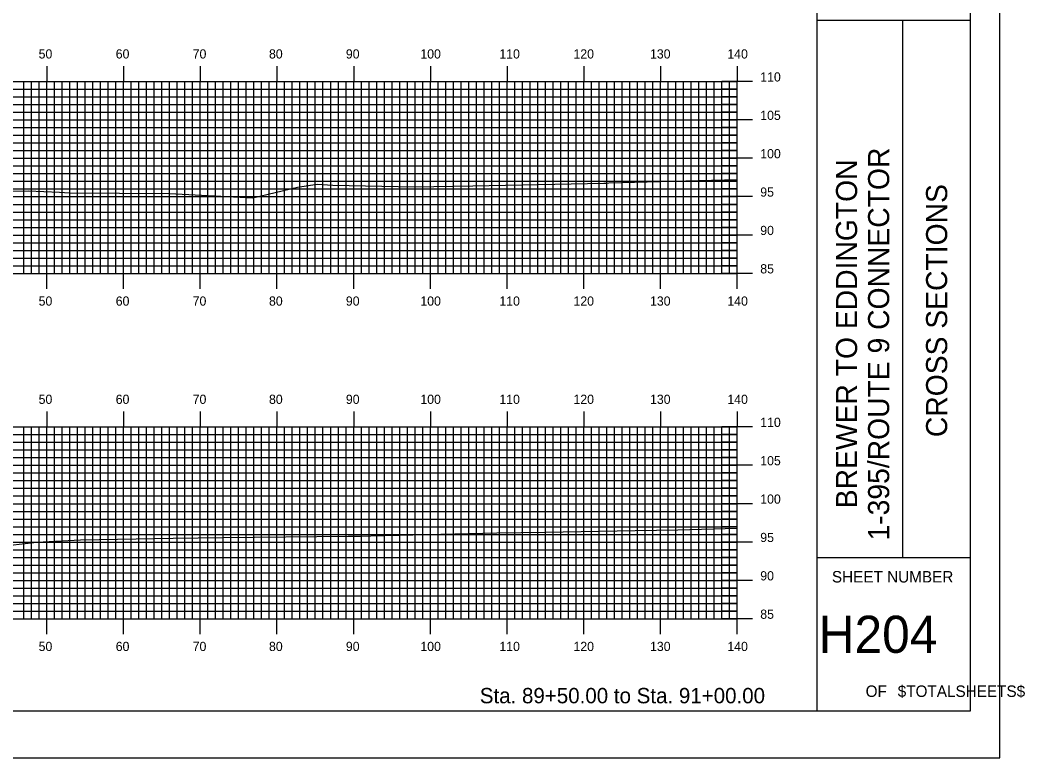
# Model space of a CAD drawing. Extents: x 1764546 to 1764889, y 442591 to 442811.
# Drawn here: x 1764757.9 to 1764888.8, y 442590.5 to 442686.7 of the extents above; entities that cross this region are included whole.
import ezdxf

# ---------------------------------------------------------------- set-up
doc = ezdxf.new("R2010")
doc.units = 0
for name, color, linetype in [('BORDER', 7, 'Continuous'), ('H_V ANNOTATION', 7, 'Continuous'), ('MAJOR', 7, 'Continuous'), ('MINOR', 7, 'Continuous'), ('PLOT BOUNDARY', 7, 'Continuous'), ('S_Roadway_Centerline', 7, 'Continuous')]:
    doc.layers.add(name, color=color, linetype=linetype)

msp = doc.modelspace()

# ---------------------------------------------------------------- linework, layer by layer
at = {"layer": 'BORDER'}
for p, q in [((1764861.74, 442596.67), (1764861.74, 442806.67)), ((1764861.74, 442686.67), (1764881.74, 442686.67)), ((1764872.93, 442616.67), (1764872.93, 442686.67)), ((1764861.74, 442616.67), (1764881.74, 442616.67))]:
    msp.add_line(p, q, dxfattribs=at)
msp.add_lwpolyline([(1764561.74, 442596.67), (1764881.74, 442596.67), (1764881.74, 442806.67), (1764561.74, 442806.67)], close=True, dxfattribs=at)
at = {"layer": 'MAJOR'}
for p, q in [((1764761.34, 442680.67), (1764761.34, 442678.67)), ((1764771.34, 442680.67), (1764771.34, 442678.67)), ((1764781.34, 442680.67), (1764781.34, 442678.67)), ((1764791.34, 442680.67), (1764791.34, 442678.67)), ((1764801.34, 442680.67), (1764801.34, 442678.67)), ((1764811.34, 442680.67), (1764811.34, 442678.67)), ((1764821.34, 442680.67), (1764821.34, 442678.67)), ((1764831.34, 442680.67), (1764831.34, 442678.67)), ((1764841.34, 442680.67), (1764841.34, 442678.67)), ((1764851.34, 442680.67), (1764851.34, 442678.67)), ((1764571.34, 442678.67), (1764851.34, 442678.67)), ((1764571.34, 442678.67), (1764851.34, 442678.67)), ((1764761.34, 442653.67), (1764761.34, 442678.67)), ((1764771.34, 442653.67), (1764771.34, 442678.67)), ((1764781.34, 442653.67), (1764781.34, 442678.67)), ((1764791.34, 442653.67), (1764791.34, 442678.67)), ((1764801.34, 442653.67), (1764801.34, 442678.67)), ((1764811.34, 442653.67), (1764811.34, 442678.67)), ((1764821.34, 442653.67), (1764821.34, 442678.67)), ((1764831.34, 442653.67), (1764831.34, 442678.67)), ((1764841.34, 442653.67), (1764841.34, 442678.67)), ((1764853.35, 442678.67), (1764849.34, 442678.67)), ((1764851.34, 442653.67), (1764851.34, 442678.67)), ((1764851.34, 442653.67), (1764851.34, 442678.67)), ((1764571.34, 442673.67), (1764851.34, 442673.67)), ((1764853.35, 442673.67), (1764849.34, 442673.67)), ((1764571.34, 442668.67), (1764851.34, 442668.67)), ((1764853.35, 442668.67), (1764849.34, 442668.67)), ((1764571.34, 442663.67), (1764851.34, 442663.67)), ((1764853.35, 442663.67), (1764849.34, 442663.67)), ((1764571.34, 442658.67), (1764851.34, 442658.67)), ((1764853.35, 442658.67), (1764849.34, 442658.67)), ((1764571.34, 442653.67), (1764851.34, 442653.67)), ((1764571.34, 442653.67), (1764851.34, 442653.67)), ((1764761.34, 442651.66), (1764761.34, 442653.67)), ((1764771.34, 442651.66), (1764771.34, 442653.67)), ((1764781.34, 442651.66), (1764781.34, 442653.67)), ((1764791.34, 442651.66), (1764791.34, 442653.67)), ((1764801.34, 442651.66), (1764801.34, 442653.67)), ((1764811.34, 442651.66), (1764811.34, 442653.67)), ((1764821.34, 442651.66), (1764821.34, 442653.67)), ((1764831.34, 442651.66), (1764831.34, 442653.67)), ((1764841.34, 442651.66), (1764841.34, 442653.67)), ((1764853.35, 442653.67), (1764849.34, 442653.67)), ((1764851.34, 442651.66), (1764851.34, 442653.67)), ((1764761.34, 442635.67), (1764761.34, 442633.67)), ((1764771.34, 442635.67), (1764771.34, 442633.67)), ((1764781.34, 442635.67), (1764781.34, 442633.67)), ((1764791.34, 442635.67), (1764791.34, 442633.67)), ((1764801.34, 442635.67), (1764801.34, 442633.67)), ((1764811.34, 442635.67), (1764811.34, 442633.67)), ((1764821.34, 442635.67), (1764821.34, 442633.67)), ((1764831.34, 442635.67), (1764831.34, 442633.67)), ((1764841.34, 442635.67), (1764841.34, 442633.67)), ((1764851.34, 442635.67), (1764851.34, 442633.67)), ((1764571.34, 442633.67), (1764851.34, 442633.67)), ((1764571.34, 442633.67), (1764851.34, 442633.67)), ((1764761.34, 442608.67), (1764761.34, 442633.67)), ((1764771.34, 442608.67), (1764771.34, 442633.67)), ((1764781.34, 442608.67), (1764781.34, 442633.67)), ((1764791.34, 442608.67), (1764791.34, 442633.67)), ((1764801.34, 442608.67), (1764801.34, 442633.67)), ((1764811.34, 442608.67), (1764811.34, 442633.67)), ((1764821.34, 442608.67), (1764821.34, 442633.67)), ((1764831.34, 442608.67), (1764831.34, 442633.67)), ((1764841.34, 442608.67), (1764841.34, 442633.67)), ((1764853.35, 442633.67), (1764849.34, 442633.67)), ((1764851.34, 442608.67), (1764851.34, 442633.67)), ((1764851.34, 442608.67), (1764851.34, 442633.67)), ((1764571.34, 442628.67), (1764851.34, 442628.67)), ((1764853.35, 442628.67), (1764849.34, 442628.67)), ((1764571.34, 442623.67), (1764851.34, 442623.67)), ((1764853.35, 442623.67), (1764849.34, 442623.67)), ((1764571.34, 442618.67), (1764851.34, 442618.67)), ((1764853.35, 442618.67), (1764849.34, 442618.67)), ((1764571.34, 442613.67), (1764851.34, 442613.67)), ((1764853.35, 442613.67), (1764849.34, 442613.67)), ((1764571.34, 442608.67), (1764851.34, 442608.67)), ((1764571.34, 442608.67), (1764851.34, 442608.67)), ((1764761.34, 442606.66), (1764761.34, 442608.67)), ((1764771.34, 442606.66), (1764771.34, 442608.67)), ((1764781.34, 442606.66), (1764781.34, 442608.67)), ((1764791.34, 442606.66), (1764791.34, 442608.67)), ((1764801.34, 442606.66), (1764801.34, 442608.67)), ((1764811.34, 442606.66), (1764811.34, 442608.67)), ((1764821.34, 442606.66), (1764821.34, 442608.67)), ((1764831.34, 442606.66), (1764831.34, 442608.67)), ((1764841.34, 442606.66), (1764841.34, 442608.67)), ((1764853.35, 442608.67), (1764849.34, 442608.67)), ((1764851.34, 442606.66), (1764851.34, 442608.67))]:
    msp.add_line(p, q, dxfattribs=at)
at = {"layer": 'MINOR'}
for p, q in [((1764758.34, 442653.67), (1764758.34, 442678.67)), ((1764759.34, 442653.67), (1764759.34, 442678.67)), ((1764760.34, 442653.67), (1764760.34, 442678.67)), ((1764762.34, 442653.67), (1764762.34, 442678.67)), ((1764763.34, 442653.67), (1764763.34, 442678.67)), ((1764764.34, 442653.67), (1764764.34, 442678.67)), ((1764765.34, 442653.67), (1764765.34, 442678.67)), ((1764766.34, 442653.67), (1764766.34, 442678.67)), ((1764767.34, 442653.67), (1764767.34, 442678.67)), ((1764768.34, 442653.67), (1764768.34, 442678.67)), ((1764769.34, 442653.67), (1764769.34, 442678.67)), ((1764770.34, 442653.67), (1764770.34, 442678.67)), ((1764772.34, 442653.67), (1764772.34, 442678.67)), ((1764773.34, 442653.67), (1764773.34, 442678.67)), ((1764774.34, 442653.67), (1764774.34, 442678.67)), ((1764775.34, 442653.67), (1764775.34, 442678.67)), ((1764776.34, 442653.67), (1764776.34, 442678.67)), ((1764777.34, 442653.67), (1764777.34, 442678.67)), ((1764778.34, 442653.67), (1764778.34, 442678.67)), ((1764779.34, 442653.67), (1764779.34, 442678.67)), ((1764780.34, 442653.67), (1764780.34, 442678.67)), ((1764782.34, 442653.67), (1764782.34, 442678.67)), ((1764783.34, 442653.67), (1764783.34, 442678.67)), ((1764784.34, 442653.67), (1764784.34, 442678.67)), ((1764785.34, 442653.67), (1764785.34, 442678.67)), ((1764786.34, 442653.67), (1764786.34, 442678.67)), ((1764787.34, 442653.67), (1764787.34, 442678.67)), ((1764788.34, 442653.67), (1764788.34, 442678.67)), ((1764789.34, 442653.67), (1764789.34, 442678.67)), ((1764790.34, 442653.67), (1764790.34, 442678.67)), ((1764792.34, 442653.67), (1764792.34, 442678.67)), ((1764793.34, 442653.67), (1764793.34, 442678.67)), ((1764794.34, 442653.67), (1764794.34, 442678.67)), ((1764795.34, 442653.67), (1764795.34, 442678.67)), ((1764796.34, 442653.67), (1764796.34, 442678.67)), ((1764797.34, 442653.67), (1764797.34, 442678.67)), ((1764798.34, 442653.67), (1764798.34, 442678.67)), ((1764799.34, 442653.67), (1764799.34, 442678.67)), ((1764800.34, 442653.67), (1764800.34, 442678.67)), ((1764802.34, 442653.67), (1764802.34, 442678.67)), ((1764803.34, 442653.67), (1764803.34, 442678.67)), ((1764804.34, 442653.67), (1764804.34, 442678.67)), ((1764805.34, 442653.67), (1764805.34, 442678.67)), ((1764806.34, 442653.67), (1764806.34, 442678.67)), ((1764807.34, 442653.67), (1764807.34, 442678.67)), ((1764808.34, 442653.67), (1764808.34, 442678.67)), ((1764809.34, 442653.67), (1764809.34, 442678.67)), ((1764810.34, 442653.67), (1764810.34, 442678.67)), ((1764812.34, 442653.67), (1764812.34, 442678.67)), ((1764813.34, 442653.67), (1764813.34, 442678.67)), ((1764814.34, 442653.67), (1764814.34, 442678.67)), ((1764815.34, 442653.67), (1764815.34, 442678.67)), ((1764816.34, 442653.67), (1764816.34, 442678.67)), ((1764817.34, 442653.67), (1764817.34, 442678.67)), ((1764818.34, 442653.67), (1764818.34, 442678.67)), ((1764819.34, 442653.67), (1764819.34, 442678.67)), ((1764820.34, 442653.67), (1764820.34, 442678.67)), ((1764822.34, 442653.67), (1764822.34, 442678.67)), ((1764823.34, 442653.67), (1764823.34, 442678.67)), ((1764824.34, 442653.67), (1764824.34, 442678.67)), ((1764825.34, 442653.67), (1764825.34, 442678.67)), ((1764826.34, 442653.67), (1764826.34, 442678.67)), ((1764827.34, 442653.67), (1764827.34, 442678.67)), ((1764828.34, 442653.67), (1764828.34, 442678.67)), ((1764829.34, 442653.67), (1764829.34, 442678.67)), ((1764830.34, 442653.67), (1764830.34, 442678.67)), ((1764832.34, 442653.67), (1764832.34, 442678.67)), ((1764833.34, 442653.67), (1764833.34, 442678.67)), ((1764834.34, 442653.67), (1764834.34, 442678.67)), ((1764835.34, 442653.67), (1764835.34, 442678.67)), ((1764836.34, 442653.67), (1764836.34, 442678.67)), ((1764837.34, 442653.67), (1764837.34, 442678.67)), ((1764838.34, 442653.67), (1764838.34, 442678.67)), ((1764839.34, 442653.67), (1764839.34, 442678.67)), ((1764840.34, 442653.67), (1764840.34, 442678.67)), ((1764842.34, 442653.67), (1764842.34, 442678.67)), ((1764843.34, 442653.67), (1764843.34, 442678.67)), ((1764844.34, 442653.67), (1764844.34, 442678.67)), ((1764845.34, 442653.67), (1764845.34, 442678.67)), ((1764846.34, 442653.67), (1764846.34, 442678.67)), ((1764847.34, 442653.67), (1764847.34, 442678.67)), ((1764848.34, 442653.67), (1764848.34, 442678.67)), ((1764849.34, 442653.67), (1764849.34, 442678.67)), ((1764850.34, 442653.67), (1764850.34, 442678.67)), ((1764571.34, 442677.67), (1764851.34, 442677.67)), ((1764851.34, 442677.67), (1764849.34, 442677.67)), ((1764571.34, 442676.67), (1764851.34, 442676.67)), ((1764571.34, 442675.67), (1764851.34, 442675.67)), ((1764851.34, 442676.67), (1764849.34, 442676.67)), ((1764851.34, 442675.67), (1764849.34, 442675.67)), ((1764571.34, 442674.67), (1764851.34, 442674.67)), ((1764851.34, 442674.67), (1764849.34, 442674.67)), ((1764571.34, 442672.67), (1764851.34, 442672.67)), ((1764571.34, 442671.67), (1764851.34, 442671.67)), ((1764851.34, 442672.67), (1764849.34, 442672.67)), ((1764851.34, 442671.67), (1764849.34, 442671.67)), ((1764571.34, 442670.67), (1764851.34, 442670.67)), ((1764851.34, 442670.67), (1764849.34, 442670.67)), ((1764571.34, 442669.67), (1764851.34, 442669.67)), ((1764851.34, 442669.67), (1764849.34, 442669.67)), ((1764571.34, 442667.67), (1764851.34, 442667.67)), ((1764571.34, 442666.67), (1764851.34, 442666.67)), ((1764851.34, 442667.67), (1764849.34, 442667.67)), ((1764851.34, 442666.67), (1764849.34, 442666.67)), ((1764571.34, 442665.67), (1764851.34, 442665.67)), ((1764851.34, 442665.67), (1764849.34, 442665.67)), ((1764571.34, 442664.67), (1764851.34, 442664.67)), ((1764851.34, 442664.67), (1764849.34, 442664.67)), ((1764571.34, 442662.67), (1764851.34, 442662.67)), ((1764851.34, 442662.67), (1764849.34, 442662.67)), ((1764571.34, 442661.67), (1764851.34, 442661.67)), ((1764851.34, 442661.67), (1764849.34, 442661.67)), ((1764571.34, 442660.67), (1764851.34, 442660.67)), ((1764851.34, 442660.67), (1764849.34, 442660.67)), ((1764571.34, 442659.67), (1764851.34, 442659.67)), ((1764851.34, 442659.67), (1764849.34, 442659.67)), ((1764571.34, 442657.67), (1764851.34, 442657.67)), ((1764851.34, 442657.67), (1764849.34, 442657.67)), ((1764571.34, 442656.67), (1764851.34, 442656.67)), ((1764851.34, 442656.67), (1764849.34, 442656.67)), ((1764571.34, 442655.67), (1764851.34, 442655.67)), ((1764571.34, 442654.67), (1764851.34, 442654.67)), ((1764851.34, 442655.67), (1764849.34, 442655.67)), ((1764851.34, 442654.67), (1764849.34, 442654.67)), ((1764571.34, 442632.67), (1764851.34, 442632.67)), ((1764758.34, 442608.67), (1764758.34, 442633.67)), ((1764759.34, 442608.67), (1764759.34, 442633.67)), ((1764760.34, 442608.67), (1764760.34, 442633.67)), ((1764762.34, 442608.67), (1764762.34, 442633.67)), ((1764763.34, 442608.67), (1764763.34, 442633.67)), ((1764764.34, 442608.67), (1764764.34, 442633.67)), ((1764765.34, 442608.67), (1764765.34, 442633.67)), ((1764766.34, 442608.67), (1764766.34, 442633.67)), ((1764767.34, 442608.67), (1764767.34, 442633.67)), ((1764768.34, 442608.67), (1764768.34, 442633.67)), ((1764769.34, 442608.67), (1764769.34, 442633.67)), ((1764770.34, 442608.67), (1764770.34, 442633.67)), ((1764772.34, 442608.67), (1764772.34, 442633.67)), ((1764773.34, 442608.67), (1764773.34, 442633.67)), ((1764774.34, 442608.67), (1764774.34, 442633.67)), ((1764775.34, 442608.67), (1764775.34, 442633.67)), ((1764776.34, 442608.67), (1764776.34, 442633.67)), ((1764777.34, 442608.67), (1764777.34, 442633.67)), ((1764778.34, 442608.67), (1764778.34, 442633.67)), ((1764779.34, 442608.67), (1764779.34, 442633.67)), ((1764780.34, 442608.67), (1764780.34, 442633.67)), ((1764782.34, 442608.67), (1764782.34, 442633.67)), ((1764783.34, 442608.67), (1764783.34, 442633.67)), ((1764784.34, 442608.67), (1764784.34, 442633.67)), ((1764785.34, 442608.67), (1764785.34, 442633.67)), ((1764786.34, 442608.67), (1764786.34, 442633.67)), ((1764787.34, 442608.67), (1764787.34, 442633.67)), ((1764788.34, 442608.67), (1764788.34, 442633.67)), ((1764789.34, 442608.67), (1764789.34, 442633.67)), ((1764790.34, 442608.67), (1764790.34, 442633.67)), ((1764792.34, 442608.67), (1764792.34, 442633.67)), ((1764793.34, 442608.67), (1764793.34, 442633.67)), ((1764794.34, 442608.67), (1764794.34, 442633.67)), ((1764795.34, 442608.67), (1764795.34, 442633.67)), ((1764796.34, 442608.67), (1764796.34, 442633.67)), ((1764797.34, 442608.67), (1764797.34, 442633.67)), ((1764798.34, 442608.67), (1764798.34, 442633.67)), ((1764799.34, 442608.67), (1764799.34, 442633.67)), ((1764800.34, 442608.67), (1764800.34, 442633.67)), ((1764802.34, 442608.67), (1764802.34, 442633.67)), ((1764803.34, 442608.67), (1764803.34, 442633.67)), ((1764804.34, 442608.67), (1764804.34, 442633.67)), ((1764805.34, 442608.67), (1764805.34, 442633.67)), ((1764806.34, 442608.67), (1764806.34, 442633.67)), ((1764807.34, 442608.67), (1764807.34, 442633.67)), ((1764808.34, 442608.67), (1764808.34, 442633.67)), ((1764809.34, 442608.67), (1764809.34, 442633.67)), ((1764810.34, 442608.67), (1764810.34, 442633.67)), ((1764812.34, 442608.67), (1764812.34, 442633.67)), ((1764813.34, 442608.67), (1764813.34, 442633.67)), ((1764814.34, 442608.67), (1764814.34, 442633.67)), ((1764815.34, 442608.67), (1764815.34, 442633.67)), ((1764816.34, 442608.67), (1764816.34, 442633.67)), ((1764817.34, 442608.67), (1764817.34, 442633.67)), ((1764818.34, 442608.67), (1764818.34, 442633.67)), ((1764819.34, 442608.67), (1764819.34, 442633.67)), ((1764820.34, 442608.67), (1764820.34, 442633.67)), ((1764822.34, 442608.67), (1764822.34, 442633.67)), ((1764823.34, 442608.67), (1764823.34, 442633.67)), ((1764824.34, 442608.67), (1764824.34, 442633.67)), ((1764825.34, 442608.67), (1764825.34, 442633.67)), ((1764826.34, 442608.67), (1764826.34, 442633.67)), ((1764827.34, 442608.67), (1764827.34, 442633.67)), ((1764828.34, 442608.67), (1764828.34, 442633.67)), ((1764829.34, 442608.67), (1764829.34, 442633.67)), ((1764830.34, 442608.67), (1764830.34, 442633.67)), ((1764832.34, 442608.67), (1764832.34, 442633.67)), ((1764833.34, 442608.67), (1764833.34, 442633.67)), ((1764834.34, 442608.67), (1764834.34, 442633.67)), ((1764835.34, 442608.67), (1764835.34, 442633.67)), ((1764836.34, 442608.67), (1764836.34, 442633.67)), ((1764837.34, 442608.67), (1764837.34, 442633.67)), ((1764838.34, 442608.67), (1764838.34, 442633.67)), ((1764839.34, 442608.67), (1764839.34, 442633.67)), ((1764840.34, 442608.67), (1764840.34, 442633.67)), ((1764842.34, 442608.67), (1764842.34, 442633.67)), ((1764843.34, 442608.67), (1764843.34, 442633.67)), ((1764844.34, 442608.67), (1764844.34, 442633.67)), ((1764845.34, 442608.67), (1764845.34, 442633.67)), ((1764846.34, 442608.67), (1764846.34, 442633.67)), ((1764847.34, 442608.67), (1764847.34, 442633.67)), ((1764848.34, 442608.67), (1764848.34, 442633.67)), ((1764849.34, 442608.67), (1764849.34, 442633.67)), ((1764851.34, 442632.67), (1764849.34, 442632.67)), ((1764850.34, 442608.67), (1764850.34, 442633.67)), ((1764571.34, 442631.67), (1764851.34, 442631.67)), ((1764851.34, 442631.67), (1764849.34, 442631.67)), ((1764571.34, 442630.67), (1764851.34, 442630.67)), ((1764851.34, 442630.67), (1764849.34, 442630.67)), ((1764571.34, 442629.67), (1764851.34, 442629.67)), ((1764851.34, 442629.67), (1764849.34, 442629.67)), ((1764571.34, 442627.67), (1764851.34, 442627.67)), ((1764851.34, 442627.67), (1764849.34, 442627.67)), ((1764571.34, 442626.67), (1764851.34, 442626.67)), ((1764851.34, 442626.67), (1764849.34, 442626.67)), ((1764571.34, 442625.67), (1764851.34, 442625.67)), ((1764571.34, 442624.67), (1764851.34, 442624.67)), ((1764851.34, 442625.67), (1764849.34, 442625.67)), ((1764851.34, 442624.67), (1764849.34, 442624.67)), ((1764571.34, 442622.67), (1764851.34, 442622.67)), ((1764851.34, 442622.67), (1764849.34, 442622.67)), ((1764571.34, 442621.67), (1764851.34, 442621.67)), ((1764571.34, 442620.67), (1764851.34, 442620.67)), ((1764851.34, 442621.67), (1764849.34, 442621.67)), ((1764851.34, 442620.67), (1764849.34, 442620.67)), ((1764571.34, 442619.67), (1764851.34, 442619.67)), ((1764851.34, 442619.67), (1764849.34, 442619.67)), ((1764571.34, 442617.67), (1764851.34, 442617.67)), ((1764571.34, 442616.67), (1764851.34, 442616.67)), ((1764851.34, 442617.67), (1764849.34, 442617.67)), ((1764851.34, 442616.67), (1764849.34, 442616.67)), ((1764571.34, 442615.67), (1764851.34, 442615.67)), ((1764851.34, 442615.67), (1764849.34, 442615.67)), ((1764571.34, 442614.67), (1764851.34, 442614.67)), ((1764851.34, 442614.67), (1764849.34, 442614.67)), ((1764571.34, 442612.67), (1764851.34, 442612.67)), ((1764571.34, 442611.67), (1764851.34, 442611.67)), ((1764851.34, 442612.67), (1764849.34, 442612.67)), ((1764851.34, 442611.67), (1764849.34, 442611.67)), ((1764571.34, 442610.67), (1764851.34, 442610.67)), ((1764851.34, 442610.67), (1764849.34, 442610.67)), ((1764571.34, 442609.67), (1764851.34, 442609.67)), ((1764851.34, 442609.67), (1764849.34, 442609.67))]:
    msp.add_line(p, q, dxfattribs=at)
at = {"layer": 'PLOT BOUNDARY'}
msp.add_lwpolyline([(1764545.56, 442590.55), (1764885.56, 442590.55), (1764885.56, 442810.55), (1764545.56, 442810.55)], close=True, dxfattribs=at)
at = {"layer": 'S_Roadway_Centerline'}
for points in [[(1764752.58, 442664.4), (1764758.91, 442664.42), (1764763.01, 442664.24), (1764764.29, 442664.19), (1764777.32, 442664.08), (1764788.2, 442663.51), (1764794, 442664.89), (1764796.56, 442665.28), (1764798.64, 442665.17), (1764809.27, 442664.93), (1764816.86, 442665.08), (1764833.95, 442665.45), (1764834.22, 442665.45), (1764834.34, 442665.45), (1764834.61, 442665.46), (1764851.34, 442665.92)], [(1764754.65, 442618.05), (1764760.02, 442618.64), (1764765.72, 442618.97), (1764777.82, 442619.17), (1764784.34, 442619.26), (1764800.62, 442619.44), (1764801.82, 442619.45), (1764802.3, 442619.45), (1764803.56, 442619.49), (1764820.01, 442619.87), (1764826.29, 442619.96), (1764838.02, 442620.16), (1764843.58, 442620.28), (1764851.34, 442620.48)]]:
    msp.add_lwpolyline(points, dxfattribs=at)

# ---------------------------------------------------------------- texts
at = {"layer": 'BORDER'}
for s, p in [('1-395/ROUTE 9 CONNECTOR', (1764871.15, 442618.87)), ('BREWER TO EDDINGTON', (1764866.97, 442623.07)), ('CROSS SECTIONS', (1764878.71, 442632.34))]:
    msp.add_text(s, height=2.7557, rotation=90, dxfattribs=at).set_placement(p)
for s, height, p in [('SHEET NUMBER', 1.4905, (1764863.68, 442613.4)), ('H204', 4.839, (1764861.96, 442604.23)), ('OF', 1.491, (1764868.08, 442598.49)), ('$TOTALSHEETS$', 1.4905, (1764872.26, 442598.49))]:
    msp.add_text(s, height=height, dxfattribs=at).set_placement(p)
at = {"layer": 'H_V ANNOTATION'}
for s, height, p in [('50', 1.2, (1764760.27, 442681.67)), ('60', 1.2, (1764770.32, 442681.67)), ('70', 1.2, (1764780.35, 442681.67)), ('80', 1.2, (1764790.3, 442681.67)), ('90', 1.2, (1764800.32, 442681.67)), ('100', 1.2, (1764810.03, 442681.67)), ('110', 1.2, (1764820.33, 442681.67)), ('120', 1.2, (1764829.99, 442681.67)), ('130', 1.2, (1764839.97, 442681.67)), ('140', 1.2, (1764850.05, 442681.67)), ('110', 1.2, (1764854.34, 442678.67)), ('105', 1.2, (1764854.34, 442673.67)), ('100', 1.2, (1764854.34, 442668.67)), ('95', 1.2, (1764854.34, 442663.67)), ('90', 1.2, (1764854.34, 442658.67)), ('85', 1.2, (1764854.34, 442653.67)), ('50', 1.2, (1764760.27, 442649.47)), ('60', 1.2, (1764770.32, 442649.47)), ('70', 1.2, (1764780.35, 442649.47)), ('80', 1.2, (1764790.3, 442649.47)), ('90', 1.2, (1764800.32, 442649.47)), ('100', 1.2, (1764810.03, 442649.47)), ('110', 1.2, (1764820.33, 442649.47)), ('120', 1.2, (1764829.99, 442649.47)), ('130', 1.2, (1764839.97, 442649.47)), ('140', 1.2, (1764850.05, 442649.47)), ('50', 1.2, (1764760.27, 442636.67)), ('60', 1.2, (1764770.32, 442636.67)), ('70', 1.2, (1764780.35, 442636.67)), ('80', 1.2, (1764790.3, 442636.67)), ('90', 1.2, (1764800.32, 442636.67)), ('100', 1.2, (1764810.03, 442636.67)), ('110', 1.2, (1764820.33, 442636.67)), ('120', 1.2, (1764829.99, 442636.67)), ('130', 1.2, (1764839.97, 442636.67)), ('140', 1.2, (1764850.05, 442636.67)), ('110', 1.2, (1764854.34, 442633.67)), ('105', 1.2, (1764854.34, 442628.67)), ('100', 1.2, (1764854.34, 442623.67)), ('95', 1.2, (1764854.34, 442618.67)), ('90', 1.2, (1764854.34, 442613.67)), ('85', 1.2, (1764854.34, 442608.67)), ('50', 1.2, (1764760.27, 442604.47)), ('60', 1.2, (1764770.32, 442604.47)), ('70', 1.2, (1764780.35, 442604.47)), ('80', 1.2, (1764790.3, 442604.47)), ('90', 1.2, (1764800.32, 442604.47)), ('100', 1.2, (1764810.03, 442604.47)), ('110', 1.2, (1764820.33, 442604.47)), ('120', 1.2, (1764829.99, 442604.47)), ('130', 1.2, (1764839.97, 442604.47)), ('140', 1.2, (1764850.05, 442604.47)), ('Sta. 89+50.00 to Sta. 91+00.00', 2.0004, (1764817.78, 442597.66))]:
    msp.add_text(s, height=height, dxfattribs=at).set_placement(p)

doc.saveas('drawing.dxf')
